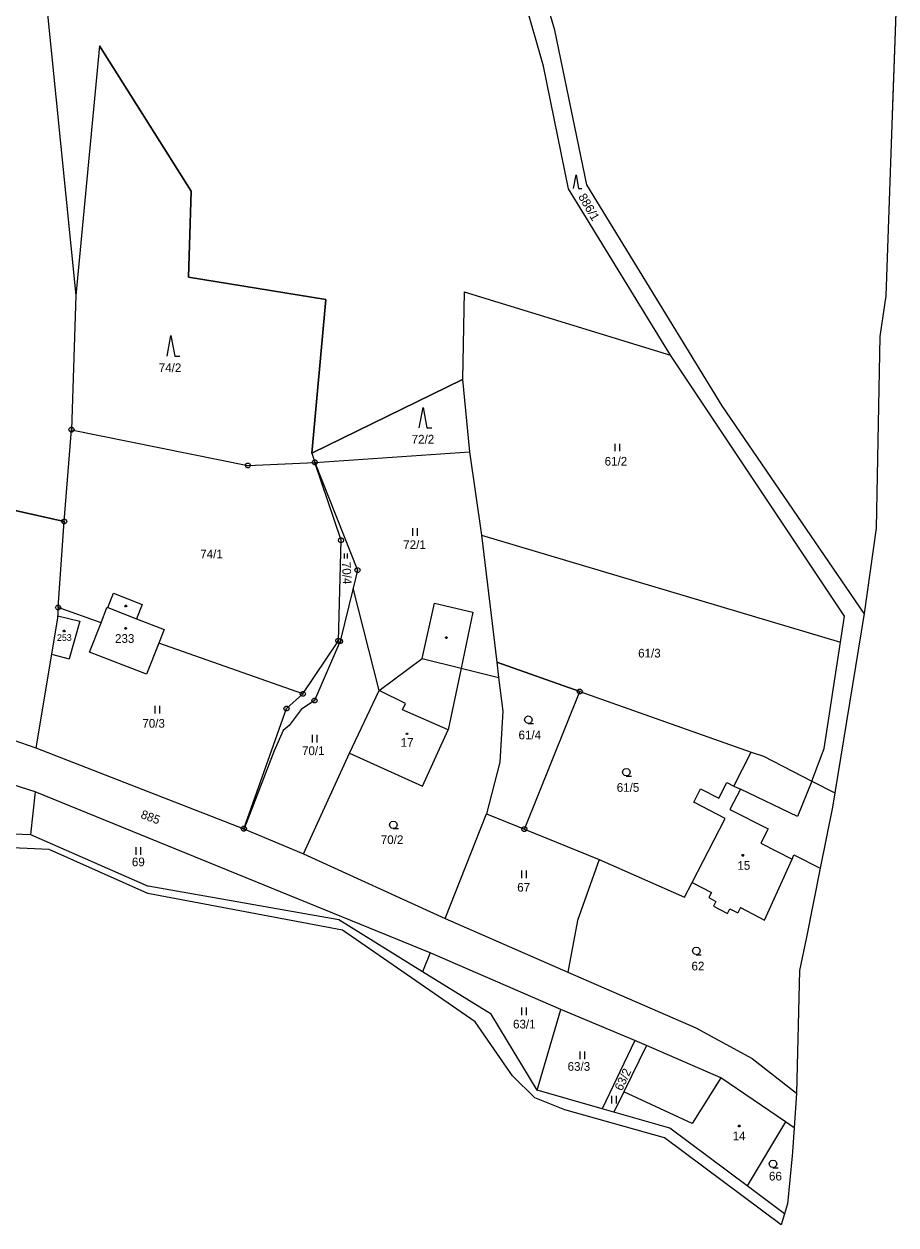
# Model space of a CAD drawing. Extents: x -580551 to -575069, y -1073031 to -1067931.
# Drawn here: x -576481.9 to -576310.9, y -1069910.2 to -1069674.8 of the extents above; entities that cross this region are included whole.
import ezdxf

# ---------------------------------------------------------------- set-up
doc = ezdxf.new("R2010")
doc.units = 0
for name, color, linetype in [('Druh pozemku', 7, 'Continuous'), ('Geodetické body', 7, 'Continuous'), ('Hranice z DKM', 7, 'Continuous'), ('Katastrální hranice', 7, 'Continuous'), ('Parcela', 7, 'Continuous'), ('Parcelní číslo', 7, 'Continuous'), ('Parcelní číslo_stavba', 7, 'Continuous'), ('SR - hranice státu', 7, 'Continuous'), ('SR - vnitřní hranice', 7, 'Continuous'), ('Vnitřní kresba', 7, 'Continuous'), ('Vrstva 6', 7, 'Continuous')]:
    doc.layers.add(name, color=color, linetype=linetype)

msp = doc.modelspace()

# ---------------------------------------------------------------- linework, layer by layer
at = {"layer": 'Druh pozemku'}
for p, q in [((-576366.03, -1069757.03), (-576366.03, -1069758.53)), ((-576365.03, -1069758.53), (-576365.03, -1069757.03)), ((-576405.72, -1069773.57), (-576405.72, -1069775.07)), ((-576404.72, -1069775.07), (-576404.72, -1069773.57)), ((-576419.115, -1069778.545), (-576419.115, -1069779.55)), ((-576418.445, -1069779.55), (-576418.445, -1069778.545)), ((-576456.22, -1069808.44), (-576456.22, -1069809.94)), ((-576455.22, -1069809.94), (-576455.22, -1069808.44)), ((-576425.38, -1069814.11), (-576425.38, -1069815.61)), ((-576424.38, -1069815.61), (-576424.38, -1069814.11)), ((-576459.96, -1069836.1), (-576459.96, -1069837.6)), ((-576458.96, -1069837.6), (-576458.96, -1069836.1)), ((-576384.33, -1069840.69), (-576384.33, -1069842.19)), ((-576383.33, -1069842.19), (-576383.33, -1069840.69)), ((-576384.34, -1069867.54), (-576384.34, -1069869.04)), ((-576383.34, -1069869.04), (-576383.34, -1069867.54)), ((-576372.9, -1069876.14), (-576372.9, -1069877.64)), ((-576371.9, -1069877.64), (-576371.9, -1069876.14)), ((-576366.68, -1069884.86), (-576366.68, -1069886.36)), ((-576365.68, -1069886.36), (-576365.68, -1069884.86))]:
    msp.add_line(p, q, dxfattribs=at)
for points in [[(-576374.132, -1069706.99), (-576373.63, -1069704.31), (-576373.128, -1069706.99), (-576372.458, -1069706.99)], [(-576453.8, -1069739.85), (-576453.05, -1069735.85), (-576452.3, -1069739.85), (-576451.3, -1069739.85)], [(-576404.38, -1069753.95), (-576403.63, -1069749.95), (-576402.88, -1069753.95), (-576401.88, -1069753.95)], [(-576382.98, -1069811.87), (-576383.36, -1069811.77), (-576383.63, -1069811.5), (-576383.73, -1069811.13), (-576383.63, -1069810.76), (-576383.36, -1069810.49), (-576382.99, -1069810.39), (-576382.62, -1069810.49), (-576382.35, -1069810.76), (-576382.25, -1069811.14), (-576382.35, -1069811.52), (-576382.62, -1069811.79), (-576383, -1069811.89), (-576382, -1069811.89)], [(-576363.76, -1069822.16), (-576364.14, -1069822.06), (-576364.41, -1069821.79), (-576364.51, -1069821.42), (-576364.41, -1069821.05), (-576364.14, -1069820.78), (-576363.77, -1069820.68), (-576363.4, -1069820.78), (-576363.13, -1069821.05), (-576363.03, -1069821.43), (-576363.13, -1069821.81), (-576363.4, -1069822.08), (-576363.78, -1069822.18), (-576362.78, -1069822.18)], [(-576409.45, -1069832.47), (-576409.83, -1069832.37), (-576410.1, -1069832.1), (-576410.2, -1069831.73), (-576410.1, -1069831.36), (-576409.83, -1069831.09), (-576409.46, -1069830.99), (-576409.09, -1069831.09), (-576408.82, -1069831.36), (-576408.72, -1069831.74), (-576408.82, -1069832.12), (-576409.09, -1069832.39), (-576409.47, -1069832.49), (-576408.47, -1069832.49)], [(-576350.04, -1069857.18), (-576350.42, -1069857.08), (-576350.69, -1069856.81), (-576350.79, -1069856.44), (-576350.69, -1069856.07), (-576350.42, -1069855.8), (-576350.05, -1069855.7), (-576349.68, -1069855.8), (-576349.41, -1069856.07), (-576349.31, -1069856.45), (-576349.41, -1069856.83), (-576349.68, -1069857.1), (-576350.06, -1069857.2), (-576349.06, -1069857.2)], [(-576335, -1069898.92), (-576335.38, -1069898.82), (-576335.65, -1069898.55), (-576335.75, -1069898.18), (-576335.65, -1069897.81), (-576335.38, -1069897.54), (-576335.01, -1069897.44), (-576334.64, -1069897.54), (-576334.37, -1069897.81), (-576334.27, -1069898.19), (-576334.37, -1069898.57), (-576334.64, -1069898.84), (-576335.02, -1069898.94), (-576334.02, -1069898.94)]]:
    msp.add_lwpolyline(points, dxfattribs=at)
for points in [[(-576461.82, -1069788.69), (-576461.73, -1069788.84), (-576461.82, -1069788.99), (-576462, -1069788.99), (-576462.09, -1069788.84), (-576462, -1069788.69)], [(-576473.92, -1069793.58), (-576473.83, -1069793.73), (-576473.92, -1069793.88), (-576474.1, -1069793.88), (-576474.19, -1069793.73), (-576474.1, -1069793.58)], [(-576461.85, -1069793.08), (-576461.76, -1069793.23), (-576461.85, -1069793.38), (-576462.03, -1069793.38), (-576462.12, -1069793.23), (-576462.03, -1069793.08)], [(-576398.97, -1069794.89), (-576398.88, -1069795.04), (-576398.97, -1069795.19), (-576399.15, -1069795.19), (-576399.24, -1069795.04), (-576399.15, -1069794.89)], [(-576406.68, -1069813.75), (-576406.59, -1069813.9), (-576406.68, -1069814.05), (-576406.86, -1069814.05), (-576406.95, -1069813.9), (-576406.86, -1069813.75)], [(-576340.83, -1069837.58), (-576340.74, -1069837.73), (-576340.83, -1069837.88), (-576341.01, -1069837.88), (-576341.1, -1069837.73), (-576341.01, -1069837.58)], [(-576341.54, -1069890.61), (-576341.45, -1069890.76), (-576341.54, -1069890.91), (-576341.72, -1069890.91), (-576341.81, -1069890.76), (-576341.72, -1069890.61)]]:
    msp.add_lwpolyline(points, close=True, dxfattribs=at)
at = {"layer": 'Geodetické body'}
for p, q in [((-576472.68, -1069754.29), (-576472.44, -1069754.29)), ((-576438.08, -1069761.31), (-576437.84, -1069761.31)), ((-576424.96, -1069760.69), (-576424.72, -1069760.69)), ((-576474.11, -1069772.28), (-576473.87, -1069772.28)), ((-576419.83, -1069775.97), (-576419.59, -1069775.97)), ((-576416.58, -1069781.82), (-576416.34, -1069781.82)), ((-576475.3, -1069789.15), (-576475.06, -1069789.15)), ((-576420.35, -1069795.67), (-576420.11, -1069795.67)), ((-576420.01, -1069795.76), (-576419.77, -1069795.76)), ((-576427.3, -1069806.08), (-576427.06, -1069806.08)), ((-576373.01, -1069805.62), (-576372.77, -1069805.62)), ((-576430.51, -1069808.96), (-576430.27, -1069808.96)), ((-576425.02, -1069807.39), (-576424.78, -1069807.39)), ((-576438.88, -1069832.51), (-576438.64, -1069832.51)), ((-576383.88, -1069832.58), (-576383.64, -1069832.58))]:
    msp.add_line(p, q, dxfattribs=at)
for points in [[(-576472.41, -1069753.81), (-576472.16, -1069753.99), (-576472.06, -1069754.28), (-576472.16, -1069754.57), (-576472.41, -1069754.75), (-576472.72, -1069754.75), (-576472.97, -1069754.57), (-576473.07, -1069754.28), (-576472.97, -1069753.99), (-576472.72, -1069753.81)], [(-576437.81, -1069760.83), (-576437.56, -1069761.01), (-576437.46, -1069761.3), (-576437.56, -1069761.59), (-576437.81, -1069761.77), (-576438.12, -1069761.77), (-576438.37, -1069761.59), (-576438.47, -1069761.3), (-576438.37, -1069761.01), (-576438.12, -1069760.83)], [(-576424.69, -1069760.21), (-576424.44, -1069760.39), (-576424.34, -1069760.68), (-576424.44, -1069760.97), (-576424.69, -1069761.15), (-576425, -1069761.15), (-576425.25, -1069760.97), (-576425.35, -1069760.68), (-576425.25, -1069760.39), (-576425, -1069760.21)], [(-576473.84, -1069771.8), (-576473.59, -1069771.98), (-576473.49, -1069772.27), (-576473.59, -1069772.56), (-576473.84, -1069772.74), (-576474.15, -1069772.74), (-576474.4, -1069772.56), (-576474.5, -1069772.27), (-576474.4, -1069771.98), (-576474.15, -1069771.8)], [(-576419.56, -1069775.49), (-576419.31, -1069775.67), (-576419.21, -1069775.96), (-576419.31, -1069776.25), (-576419.56, -1069776.43), (-576419.87, -1069776.43), (-576420.12, -1069776.25), (-576420.22, -1069775.96), (-576420.12, -1069775.67), (-576419.87, -1069775.49)], [(-576416.31, -1069781.34), (-576416.06, -1069781.52), (-576415.96, -1069781.81), (-576416.06, -1069782.1), (-576416.31, -1069782.28), (-576416.62, -1069782.28), (-576416.87, -1069782.1), (-576416.97, -1069781.81), (-576416.87, -1069781.52), (-576416.62, -1069781.34)], [(-576475.03, -1069788.67), (-576474.78, -1069788.85), (-576474.68, -1069789.14), (-576474.78, -1069789.43), (-576475.03, -1069789.61), (-576475.34, -1069789.61), (-576475.59, -1069789.43), (-576475.69, -1069789.14), (-576475.59, -1069788.85), (-576475.34, -1069788.67)], [(-576420.08, -1069795.19), (-576419.83, -1069795.37), (-576419.73, -1069795.66), (-576419.83, -1069795.95), (-576420.08, -1069796.13), (-576420.39, -1069796.13), (-576420.64, -1069795.95), (-576420.74, -1069795.66), (-576420.64, -1069795.37), (-576420.39, -1069795.19)], [(-576419.74, -1069795.28), (-576419.49, -1069795.46), (-576419.39, -1069795.75), (-576419.49, -1069796.04), (-576419.74, -1069796.22), (-576420.05, -1069796.22), (-576420.3, -1069796.04), (-576420.4, -1069795.75), (-576420.3, -1069795.46), (-576420.05, -1069795.28)], [(-576427.03, -1069805.6), (-576426.78, -1069805.78), (-576426.68, -1069806.07), (-576426.78, -1069806.36), (-576427.03, -1069806.54), (-576427.34, -1069806.54), (-576427.59, -1069806.36), (-576427.69, -1069806.07), (-576427.59, -1069805.78), (-576427.34, -1069805.6)], [(-576372.74, -1069805.14), (-576372.49, -1069805.32), (-576372.39, -1069805.61), (-576372.49, -1069805.9), (-576372.74, -1069806.08), (-576373.05, -1069806.08), (-576373.3, -1069805.9), (-576373.4, -1069805.61), (-576373.3, -1069805.32), (-576373.05, -1069805.14)], [(-576430.24, -1069808.48), (-576429.99, -1069808.66), (-576429.89, -1069808.95), (-576429.99, -1069809.24), (-576430.24, -1069809.42), (-576430.55, -1069809.42), (-576430.8, -1069809.24), (-576430.9, -1069808.95), (-576430.8, -1069808.66), (-576430.55, -1069808.48)], [(-576424.75, -1069806.91), (-576424.5, -1069807.09), (-576424.4, -1069807.38), (-576424.5, -1069807.67), (-576424.75, -1069807.85), (-576425.06, -1069807.85), (-576425.31, -1069807.67), (-576425.41, -1069807.38), (-576425.31, -1069807.09), (-576425.06, -1069806.91)], [(-576438.61, -1069832.03), (-576438.36, -1069832.21), (-576438.26, -1069832.5), (-576438.36, -1069832.79), (-576438.61, -1069832.97), (-576438.92, -1069832.97), (-576439.17, -1069832.79), (-576439.27, -1069832.5), (-576439.17, -1069832.21), (-576438.92, -1069832.03)], [(-576383.61, -1069832.1), (-576383.36, -1069832.28), (-576383.26, -1069832.57), (-576383.36, -1069832.86), (-576383.61, -1069833.04), (-576383.92, -1069833.04), (-576384.17, -1069832.86), (-576384.27, -1069832.57), (-576384.17, -1069832.28), (-576383.92, -1069832.1)]]:
    msp.add_lwpolyline(points, close=True, dxfattribs=at)
at = {"layer": 'Hranice z DKM'}
msp.add_line((-576467.05, -1069679.03), (-576471.71, -1069728.02), dxfattribs=at)
msp.add_lwpolyline([(-576467.05, -1069679.03), (-576449.1, -1069707.56), (-576449.6, -1069724.39), (-576422.66, -1069728.8), (-576425.41, -1069758.92), (-576395.91, -1069744.45), (-576394.52, -1069758.66)], dxfattribs=at)
at = {"layer": 'Katastrální hranice'}
for p, q in [((-576310.89, -1069672.53), (-576311.55, -1069690.64)), ((-576311.55, -1069690.64), (-576311.68, -1069694.55)), ((-576311.68, -1069694.55), (-576312.29, -1069711.29)), ((-576314.03, -1069736.03), (-576314.8, -1069773.62)), ((-576314.8, -1069773.62), (-576317.15, -1069790.34)), ((-576317.15, -1069790.34), (-576322.89, -1069825.47)), ((-576322.89, -1069825.47), (-576323.35, -1069828.29)), ((-576323.35, -1069828.29), (-576325.76, -1069840.24)), ((-576476.91, -1069836.55), (-576496.21, -1069835.74)), ((-576457.57, -1069845.23), (-576476.91, -1069836.55)), ((-576325.76, -1069840.24), (-576328.47, -1069853.74)), ((-576419.39, -1069852.36), (-576457.57, -1069845.23)), ((-576393.42, -1069870.34), (-576419.39, -1069852.36)), ((-576328.47, -1069853.74), (-576329.79, -1069860.29)), ((-576329.79, -1069860.29), (-576330.43, -1069884.33)), ((-576386.08, -1069880.95), (-576393.42, -1069870.34)), ((-576381.69, -1069885.26), (-576386.08, -1069880.95)), ((-576330.43, -1069884.33), (-576330.88, -1069891.13)), ((-576375.81, -1069887.58), (-576381.69, -1069885.26)), ((-576356.26, -1069893.12), (-576375.81, -1069887.58)), ((-576330.88, -1069891.13), (-576331.18, -1069895.81)), ((-576333.4, -1069910.17), (-576356.26, -1069893.12)), ((-576331.18, -1069895.81), (-576331.23, -1069896.62)), ((-576331.23, -1069896.62), (-576332.15, -1069906.02)), ((-576332.73, -1069907.96), (-576333.4, -1069910.17)), ((-576332.15, -1069906.02), (-576332.73, -1069907.96))]:
    msp.add_line(p, q, dxfattribs=at)
at = {"layer": 'Parcela'}
for p, q in [((-576379.99, -1069683.07), (-576388.54, -1069653.25)), ((-576377.77, -1069676.01), (-576384.57, -1069653.3)), ((-576371.51, -1069706.29), (-576377.77, -1069676.01)), ((-576467.05, -1069679.03), (-576471.71, -1069728.02)), ((-576449.1, -1069707.56), (-576467.05, -1069679.03)), ((-576375.09, -1069707.11), (-576379.99, -1069683.07)), ((-576449.6, -1069724.39), (-576449.1, -1069707.56)), ((-576355.08, -1069739.7), (-576375.09, -1069707.11)), ((-576345, -1069749.63), (-576371.51, -1069706.29)), ((-576422.66, -1069728.8), (-576449.6, -1069724.39)), ((-576471.71, -1069728.02), (-576472.56, -1069754.29)), ((-576425.41, -1069758.92), (-576422.66, -1069728.8)), ((-576395.54, -1069727.3), (-576395.91, -1069744.45)), ((-576395.54, -1069727.3), (-576355.08, -1069739.7)), ((-576320.97, -1069790.85), (-576355.08, -1069739.7)), ((-576395.91, -1069744.45), (-576425.41, -1069758.92)), ((-576395.91, -1069744.45), (-576394.52, -1069758.66)), ((-576317.15, -1069790.34), (-576345, -1069749.63)), ((-576473.99, -1069772.28), (-576472.56, -1069754.29)), ((-576472.56, -1069754.29), (-576437.96, -1069761.31)), ((-576425.41, -1069758.92), (-576424.84, -1069760.69)), ((-576424.84, -1069760.69), (-576394.52, -1069758.66)), ((-576394.52, -1069758.66), (-576392.14, -1069774.94)), ((-576437.96, -1069761.31), (-576424.84, -1069760.69)), ((-576424.84, -1069760.69), (-576416.46, -1069781.82)), ((-576419.71, -1069775.97), (-576424.84, -1069760.69)), ((-576473.99, -1069772.28), (-576502.1, -1069766)), ((-576475.18, -1069789.15), (-576473.99, -1069772.28)), ((-576420.23, -1069795.67), (-576419.71, -1069775.97)), ((-576392.14, -1069774.94), (-576321.76, -1069795.96)), ((-576392.14, -1069774.94), (-576389.17, -1069799.88)), ((-576416.46, -1069781.82), (-576417.32, -1069785.34)), ((-576417.32, -1069785.34), (-576419.89, -1069795.76)), ((-576412.22, -1069805.38), (-576417.32, -1069785.34)), ((-576465.41, -1069789.14), (-576464.32, -1069786.34)), ((-576464.32, -1069786.34), (-576458.68, -1069788.55)), ((-576475.18, -1069789.15), (-576475.32, -1069791.24)), ((-576466.76, -1069792.12), (-576475.18, -1069789.15)), ((-576466.76, -1069792.12), (-576465.61, -1069789.15)), ((-576465.61, -1069789.15), (-576465.41, -1069789.14)), ((-576458.68, -1069788.55), (-576459.78, -1069791.34)), ((-576403.79, -1069799.12), (-576401.4, -1069788.29)), ((-576401.4, -1069788.29), (-576393.87, -1069790.03)), ((-576393.87, -1069790.03), (-576396.17, -1069801.03)), ((-576475.32, -1069791.24), (-576479.58, -1069816.65)), ((-576475.23, -1069790.79), (-576476.46, -1069798.32)), ((-576475.23, -1069790.79), (-576470.95, -1069791.84)), ((-576470.95, -1069791.84), (-576472.99, -1069799.22)), ((-576469, -1069797.89), (-576466.76, -1069792.12)), ((-576459.78, -1069791.34), (-576454.42, -1069793.44)), ((-576321.76, -1069795.96), (-576320.97, -1069790.85)), ((-576454.42, -1069793.44), (-576455.45, -1069796.11)), ((-576455.45, -1069796.11), (-576457.82, -1069802.23)), ((-576427.18, -1069806.08), (-576455.45, -1069796.11)), ((-576427.18, -1069806.08), (-576420.23, -1069795.67)), ((-576419.89, -1069795.76), (-576424.9, -1069807.39)), ((-576324.99, -1069816.81), (-576321.76, -1069795.96)), ((-576476.46, -1069798.32), (-576472.99, -1069799.22)), ((-576457.82, -1069802.23), (-576469, -1069797.89)), ((-576412.22, -1069805.38), (-576403.79, -1069799.12)), ((-576396.17, -1069801.03), (-576398.71, -1069813.13)), ((-576396.17, -1069801.03), (-576388.8, -1069802.88)), ((-576372.89, -1069805.62), (-576389.17, -1069799.88)), ((-576389.17, -1069799.88), (-576388.8, -1069802.88)), ((-576388.8, -1069802.88), (-576387.99, -1069809.48)), ((-576430.39, -1069808.96), (-576427.18, -1069806.08)), ((-576418.07, -1069817.68), (-576412.22, -1069805.38)), ((-576383.76, -1069832.58), (-576372.89, -1069805.62)), ((-576372.89, -1069805.62), (-576339.26, -1069817.47)), ((-576438.76, -1069832.51), (-576430.39, -1069808.96)), ((-576424.9, -1069807.39), (-576427.5, -1069809.12)), ((-576497.69, -1069810.33), (-576479.58, -1069816.65)), ((-576427.5, -1069809.12), (-576429.85, -1069812.24)), ((-576387.99, -1069809.48), (-576388.59, -1069819.44)), ((-576431.07, -1069813.24), (-576432.8, -1069817.21)), ((-576429.85, -1069812.24), (-576431.07, -1069813.24)), ((-576403.73, -1069824.15), (-576398.71, -1069813.13)), ((-576479.58, -1069816.65), (-576438.76, -1069832.51)), ((-576432.8, -1069817.21), (-576438.62, -1069832.32)), ((-576427.05, -1069837.44), (-576418.07, -1069817.68)), ((-576418.07, -1069817.68), (-576403.73, -1069824.15)), ((-576342.7, -1069824.15), (-576339.26, -1069817.47)), ((-576339.26, -1069817.47), (-576336.87, -1069818.31)), ((-576336.87, -1069818.31), (-576327.39, -1069823.16)), ((-576327.39, -1069823.16), (-576324.99, -1069816.81)), ((-576479.69, -1069825.3), (-576500.03, -1069818.69)), ((-576388.59, -1069819.44), (-576391.18, -1069829.59)), ((-576327.39, -1069823.16), (-576322.89, -1069825.47)), ((-576479.69, -1069825.3), (-576480.63, -1069833.61)), ((-576402.22, -1069856.82), (-576479.69, -1069825.3)), ((-576350.56, -1069827.27), (-576349.23, -1069824.68)), ((-576349.23, -1069824.68), (-576345.62, -1069826.53)), ((-576345.62, -1069826.53), (-576344.04, -1069823.46)), ((-576344.04, -1069823.46), (-576342.7, -1069824.15)), ((-576344.36, -1069830.47), (-576350.56, -1069827.27)), ((-576399.3, -1069850.1), (-576391.18, -1069829.59)), ((-576391.18, -1069829.59), (-576383.76, -1069832.58)), ((-576438.62, -1069832.32), (-576438.76, -1069832.51)), ((-576438.76, -1069832.51), (-576427.05, -1069837.44)), ((-576383.76, -1069832.58), (-576369.08, -1069838.51)), ((-576350.83, -1069843.03), (-576344.36, -1069830.47)), ((-576504.35, -1069832.65), (-576480.63, -1069833.61)), ((-576480.63, -1069833.61), (-576457.52, -1069843.77)), ((-576427.05, -1069837.44), (-576399.3, -1069850.1)), ((-576369.08, -1069838.51), (-576373.34, -1069850.48)), ((-576369.08, -1069838.51), (-576352.39, -1069845.89)), ((-576336.7, -1069850.42), (-576331.26, -1069838.44)), ((-576331.26, -1069838.44), (-576330.9, -1069837.64)), ((-576330.9, -1069837.64), (-576325.76, -1069840.24)), ((-576420.17, -1069850.39), (-576457.52, -1069843.77)), ((-576352.39, -1069845.89), (-576350.83, -1069843.03)), ((-576350.83, -1069843.03), (-576347.09, -1069844.99)), ((-576347.09, -1069844.99), (-576347.61, -1069846)), ((-576347.61, -1069846), (-576346.19, -1069846.75)), ((-576346.19, -1069846.75), (-576346.68, -1069847.71)), ((-576346.68, -1069847.71), (-576343.94, -1069849.14)), ((-576343.94, -1069849.14), (-576343.45, -1069848.2)), ((-576343.45, -1069848.2), (-576341.92, -1069849.01)), ((-576341.38, -1069847.97), (-576341.92, -1069849.01)), ((-576341.38, -1069847.97), (-576336.7, -1069850.42)), ((-576403.72, -1069860.55), (-576420.17, -1069850.39)), ((-576399.3, -1069850.1), (-576375.22, -1069860.59)), ((-576373.34, -1069850.48), (-576375.22, -1069860.59)), ((-576402.22, -1069856.82), (-576403.72, -1069860.55)), ((-576376.62, -1069867.91), (-576402.22, -1069856.82)), ((-576390.24, -1069868.88), (-576403.72, -1069860.55)), ((-576375.22, -1069860.59), (-576350.12, -1069871.53)), ((-576381.22, -1069883.77), (-576376.62, -1069867.91)), ((-576362.08, -1069874.03), (-576376.62, -1069867.91)), ((-576381.22, -1069883.77), (-576390.24, -1069868.88)), ((-576350.12, -1069871.53), (-576339.08, -1069877.57)), ((-576362.08, -1069874.03), (-576368.48, -1069887.42)), ((-576359.78, -1069875), (-576364.26, -1069884.07)), ((-576359.78, -1069875), (-576362.08, -1069874.03)), ((-576345.23, -1069881.35), (-576359.78, -1069875)), ((-576339.08, -1069877.57), (-576330.43, -1069884.33)), ((-576332.56, -1069889.98), (-576345.23, -1069881.35)), ((-576368.48, -1069887.42), (-576381.22, -1069883.77)), ((-576364.26, -1069884.07), (-576366.24, -1069888.06)), ((-576366.24, -1069888.06), (-576368.48, -1069887.42)), ((-576355.22, -1069891.21), (-576366.24, -1069888.06)), ((-576340.08, -1069902.48), (-576355.22, -1069891.21)), ((-576332.56, -1069889.98), (-576340.08, -1069902.48)), ((-576330.88, -1069891.13), (-576332.56, -1069889.98)), ((-576332.73, -1069907.96), (-576340.08, -1069902.48))]:
    msp.add_line(p, q, dxfattribs=at)
at = {"layer": 'SR - hranice státu'}
for points in [[(-576502.1, -1069766), (-576473.99, -1069772.28), (-576472.56, -1069754.29), (-576437.96, -1069761.31), (-576424.84, -1069760.69)], [(-576424.84, -1069760.69), (-576394.52, -1069758.66), (-576392.14, -1069774.94), (-576389.17, -1069799.88)], [(-576389.17, -1069799.88), (-576372.89, -1069805.62), (-576339.26, -1069817.47), (-576336.87, -1069818.31), (-576327.39, -1069823.16), (-576322.89, -1069825.47)]]:
    msp.add_lwpolyline(points, dxfattribs=at)
at = {"layer": 'SR - vnitřní hranice'}
msp.add_lwpolyline([(-576315.89, -1069625.25), (-576314.83, -1069640.97), (-576310.89, -1069672.53), (-576311.68, -1069694.55), (-576312.29, -1069711.29), (-576312.9, -1069728.03), (-576314.03, -1069736.03), (-576314.8, -1069773.62), (-576317.15, -1069790.34), (-576322.89, -1069825.47)], dxfattribs=at)
at = {"layer": 'Vnitřní kresba'}
for p, q in [((-576465.41, -1069789.14), (-576459.78, -1069791.34)), ((-576403.79, -1069799.12), (-576396.17, -1069801.03)), ((-576407.06, -1069807.99), (-576412.22, -1069805.38)), ((-576407.65, -1069809.21), (-576407.06, -1069807.99)), ((-576398.71, -1069813.13), (-576407.65, -1069809.21)), ((-576327.39, -1069823.16), (-576330.22, -1069830.12)), ((-576341.41, -1069824.78), (-576343.45, -1069828.71)), ((-576342.7, -1069824.15), (-576341.41, -1069824.78)), ((-576330.22, -1069830.12), (-576341.41, -1069824.78)), ((-576343.45, -1069828.71), (-576335.95, -1069832.54)), ((-576335.95, -1069832.54), (-576337.36, -1069835.34)), ((-576337.36, -1069835.34), (-576331.26, -1069838.44)), ((-576345.23, -1069881.35), (-576350.84, -1069890.28)), ((-576350.84, -1069890.28), (-576364.26, -1069884.07))]:
    msp.add_line(p, q, dxfattribs=at)
at = {"layer": 'Vrstva 6'}
msp.add_line((-576479.74, -1069648.52), (-576471.71, -1069728.02), dxfattribs=at)

# ---------------------------------------------------------------- texts
at = {"layer": 'Parcelní číslo'}
for s, rotation, p in [('886/1', 300.11529, (-576373.26, -1069708.604)), ('70/4', 272.55602, (-576419.527, -1069780.233)), ('885', 339.64938, (-576459.13, -1069830.36)), ('63/2', 64.80153, (-576364.621, -1069884.009))]:
    msp.add_text(s, height=1.7, rotation=rotation, dxfattribs=at).set_placement(p)
for s, p in [('74/2', (-576455.451, -1069743)), ('72/2', (-576405.856, -1069757)), ('61/2', (-576368.019, -1069761.33)), ('72/1', (-576407.514, -1069777.67)), ('74/1', (-576447.309, -1069779.5)), ('61/3', (-576361.451, -1069798.94)), ('70/3', (-576458.666, -1069812.7)), ('61/4', (-576384.904, -1069814.97)), ('70/1', (-576427.362, -1069818.07)), ('61/5', (-576365.645, -1069825.27)), ('70/2', (-576411.914, -1069835.5)), ('69', (-576460.716, -1069839.86)), ('67', (-576385.161, -1069844.83)), ('62', (-576350.991, -1069860.27)), ('63/1', (-576385.981, -1069871.65)), ('63/3', (-576375.285, -1069879.95)), ('66', (-576335.796, -1069901.45))]:
    msp.add_text(s, height=1.7, dxfattribs=at).set_placement(p)
at = {"layer": 'Parcelní číslo_stavba'}
for s, height, p in [('253', 1.3, (-576475.409, -1069795.68)), ('233', 1.7, (-576464.023, -1069796.07)), ('17', 1.7, (-576408.024, -1069816.45)), ('15', 1.7, (-576341.99, -1069840.55)), ('14', 1.7, (-576342.919, -1069893.55))]:
    msp.add_text(s, height=height, dxfattribs=at).set_placement(p)

doc.saveas('drawing.dxf')
